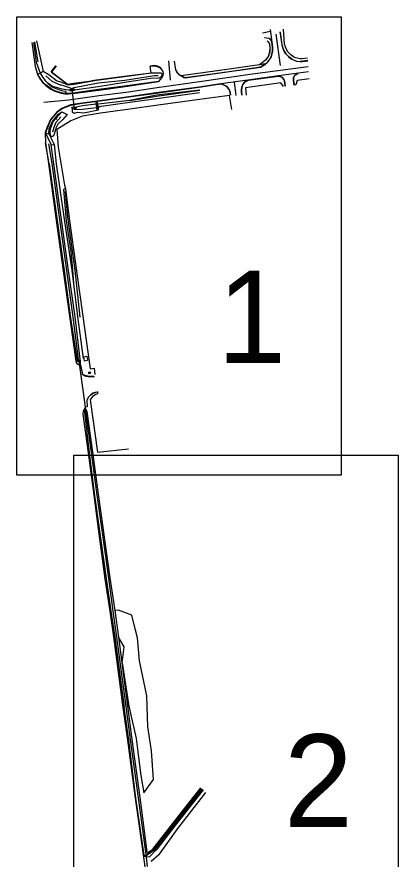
# Model space of a CAD drawing. Extents: x -866693 to -866303, y -1041966 to -1040244.
# Drawn here: x -866357.09 to -866344.74, y -1041790.49 to -1041763.2 of the extents above; entities that cross this region are included whole.
import ezdxf

# ---------------------------------------------------------------- set-up
doc = ezdxf.new("R2010")
doc.units = 0
doc.layers.add('Formát', color=7, linetype='Continuous')
doc.layers.add('Legenda', color=7, linetype='Continuous')

msp = doc.modelspace()

# ---------------------------------------------------------------- linework, layer by layer
at = {"layer": 'Legenda'}
for p, q in [((-866348.876, -1041763.675), (-866349.136, -1041763.734)), ((-866348.826, -1041764.023), (-866348.875, -1041763.608)), ((-866356.452, -1041763.975), (-866356.243, -1041764.972)), ((-866348.708, -1041763.762), (-866348.566, -1041764.773)), ((-866356.609, -1041764.036), (-866356.499, -1041764.813)), ((-866356.555, -1041764.03), (-866356.468, -1041764.665)), ((-866356.406, -1041764.659), (-866356.509, -1041764.007)), ((-866356.468, -1041764.665), (-866356.333, -1041765.029)), ((-866352.746, -1041765.022), (-866352.779, -1041764.799)), ((-866352.739, -1041765.027), (-866352.771, -1041764.804)), ((-866352.184, -1041764.624), (-866352.13, -1041765.247)), ((-866349.046, -1041764.728), (-866349.228, -1041764.754)), ((-866352.417, -1041765.021), (-866352.739, -1041765.027)), ((-866349.985, -1041765.749), (-866350.047, -1041765.314)), ((-866349.517, -1041765.253), (-866349.518, -1041765.249)), ((-866348.617, -1041765.135), (-866349.517, -1041765.253)), ((-866355.511, -1041765.61), (-866355.523, -1041765.68)), ((-866355.305, -1041765.551), (-866355.308, -1041765.527)), ((-866355.229, -1041766.165), (-866355.305, -1041765.55)), ((-866352.57, -1041765.771), (-866351.171, -1041765.58)), ((-866353.434, -1041765.908), (-866352.57, -1041765.771)), ((-866355.306, -1041766.168), (-866355.246, -1041766.167)), ((-866355.227, -1041766.199), (-866355.225, -1041766.165)), ((-866354.97, -1041766.083), (-866355.159, -1041766.122)), ((-866355.797, -1041766.529), (-866355.822, -1041766.493)), ((-866356.159, -1041766.964), (-866355.98, -1041767.349)), ((-866356.061, -1041766.989), (-866355.888, -1041767.34)), ((-866356.041, -1041767.959), (-866356.162, -1041767.281)), ((-866355.29, -1041771.401), (-866355.262, -1041771.827)), ((-866355.088, -1041774.36), (-866354.872, -1041775.924)), ((-866354.932, -1041774.212), (-866354.821, -1041774.197)), ((-866354.932, -1041774.212), (-866354.914, -1041774.341)), ((-866354.931, -1041774.213), (-866354.823, -1041774.198)), ((-866354.931, -1041774.213), (-866354.913, -1041774.34)), ((-866354.914, -1041774.341), (-866354.803, -1041774.326)), ((-866354.913, -1041774.34), (-866354.805, -1041774.325)), ((-866354.823, -1041774.198), (-866354.805, -1041774.325)), ((-866354.821, -1041774.197), (-866354.803, -1041774.326)), ((-866354.776, -1041774.71), (-866354.716, -1041774.703)), ((-866354.776, -1041774.71), (-866354.772, -1041774.754)), ((-866354.774, -1041774.712), (-866354.717, -1041774.705)), ((-866354.774, -1041774.712), (-866354.771, -1041774.752)), ((-866354.772, -1041774.754), (-866354.712, -1041774.747)), ((-866354.771, -1041774.752), (-866354.714, -1041774.745)), ((-866354.717, -1041774.705), (-866354.714, -1041774.745)), ((-866354.716, -1041774.703), (-866354.712, -1041774.747)), ((-866354.708, -1041775.46), (-866354.768, -1041775.526)), ((-866354.624, -1041775.399), (-866354.708, -1041775.46)), ((-866354.509, -1041775.357), (-866354.624, -1041775.399)), ((-866354.509, -1041775.357), (-866354.512, -1041775.354)), ((-866354.824, -1041775.621), (-866354.829, -1041775.618)), ((-866354.768, -1041775.526), (-866354.824, -1041775.621)), ((-866354.898, -1041775.902), (-866354.904, -1041776.005)), ((-866354.904, -1041776.005), (-866354.746, -1041777.325)), ((-866354.872, -1041775.924), (-866354.866, -1041775.986)), ((-866354.866, -1041775.986), (-866354.688, -1041777.315)), ((-866354.823, -1041775.985), (-866354.643, -1041777.308)), ((-866354.746, -1041777.325), (-866354.572, -1041778.706)), ((-866354.688, -1041777.315), (-866354.502, -1041778.697)), ((-866354.643, -1041777.308), (-866354.46, -1041778.663)), ((-866354.572, -1041778.706), (-866354.425, -1041779.772)), ((-866354.502, -1041778.697), (-866354.354, -1041779.755)), ((-866354.46, -1041778.663), (-866354.308, -1041779.74)), ((-866354.425, -1041779.772), (-866354.196, -1041781.395)), ((-866354.354, -1041779.755), (-866354.129, -1041781.381)), ((-866354.308, -1041779.74), (-866354.077, -1041781.37)), ((-866354.196, -1041781.395), (-866354.045, -1041782.456)), ((-866354.129, -1041781.381), (-866353.984, -1041782.449)), ((-866354.077, -1041781.37), (-866353.924, -1041782.429)), ((-866354.045, -1041782.456), (-866353.924, -1041783.291)), ((-866353.984, -1041782.449), (-866353.866, -1041783.294)), ((-866353.8, -1041782.422), (-866353.924, -1041782.429)), ((-866353.924, -1041782.429), (-866353.796, -1041783.301)), ((-866353.373, -1041782.588), (-866353.8, -1041782.422)), ((-866353.255, -1041783.029), (-866353.373, -1041782.588)), ((-866353.19, -1041783.317), (-866353.255, -1041783.029)), ((-866353.924, -1041783.291), (-866353.617, -1041785.568)), ((-866353.866, -1041783.294), (-866353.558, -1041785.547)), ((-866353.796, -1041783.301), (-866353.51, -1041785.536)), ((-866353.621, -1041783.609), (-866353.796, -1041783.301)), ((-866353.121, -1041784.06), (-866353.19, -1041783.317)), ((-866353.681, -1041784.123), (-866353.621, -1041783.609)), ((-866353.681, -1041784.123), (-866353.47, -1041785.529)), ((-866352.877, -1041785.197), (-866353.121, -1041784.06)), ((-866352.853, -1041786.204), (-866352.877, -1041785.197)), ((-866353.558, -1041785.547), (-866353.417, -1041786.616)), ((-866353.51, -1041785.536), (-866353.363, -1041786.612)), ((-866353.47, -1041785.529), (-866353.232, -1041786.582)), ((-866353.465, -1041786.632), (-866353.617, -1041785.568)), ((-866352.731, -1041786.979), (-866352.853, -1041786.204)), ((-866353.238, -1041788.51), (-866353.465, -1041786.632)), ((-866353.417, -1041786.616), (-866353.163, -1041788.5)), ((-866353.363, -1041786.612), (-866353.108, -1041788.493)), ((-866353.232, -1041786.582), (-866353.147, -1041787.179)), ((-866353.147, -1041787.179), (-866353.077, -1041787.777)), ((-866352.667, -1041787.909), (-866352.731, -1041786.979)), ((-866353.077, -1041787.777), (-866352.983, -1041788.336)), ((-866352.983, -1041788.336), (-866352.667, -1041787.909)), ((-866352.044, -1041789.33), (-866351.131, -1041788.18)), ((-866352.035, -1041789.354), (-866351.113, -1041788.193)), ((-866351.078, -1041788.218), (-866352.01, -1041789.373)), ((-866351.062, -1041788.236), (-866351.973, -1041789.406)), ((-866352.973, -1041790.356), (-866353.238, -1041788.51)), ((-866353.163, -1041788.5), (-866352.91, -1041790.339)), ((-866353.108, -1041788.493), (-866352.883, -1041790.247)), ((-866351.879, -1041789.489), (-866350.973, -1041788.332)), ((-866352.684, -1041790.168), (-866352.044, -1041789.33)), ((-866352.666, -1041790.181), (-866352.035, -1041789.354)), ((-866352.01, -1041789.373), (-866352.641, -1041790.199)), ((-866351.973, -1041789.406), (-866352.546, -1041790.157)), ((-866352.468, -1041790.32), (-866351.879, -1041789.489)), ((-866352.848, -1041790.275), (-866352.684, -1041790.168)), ((-866352.848, -1041790.316), (-866352.666, -1041790.181)), ((-866352.579, -1041790.197), (-866352.612, -1041790.22)), ((-866352.546, -1041790.157), (-866352.579, -1041790.197)), ((-866352.962, -1041790.403), (-866353.006, -1041790.332)), ((-866352.961, -1041790.371), (-866352.973, -1041790.356)), ((-866352.869, -1041790.421), (-866352.962, -1041790.403)), ((-866352.93, -1041790.383), (-866352.961, -1041790.371)), ((-866352.891, -1041790.377), (-866352.93, -1041790.383)), ((-866352.91, -1041790.339), (-866352.848, -1041790.316)), ((-866352.91, -1041790.339), (-866352.867, -1041790.725)), ((-866352.857, -1041790.348), (-866352.891, -1041790.377)), ((-866352.883, -1041790.247), (-866352.866, -1041790.271)), ((-866352.795, -1041790.415), (-866352.869, -1041790.421)), ((-866352.866, -1041790.271), (-866352.848, -1041790.275)), ((-866352.834, -1041790.341), (-866352.857, -1041790.348)), ((-866352.641, -1041790.199), (-866352.834, -1041790.341)), ((-866352.612, -1041790.22), (-866352.795, -1041790.415)), ((-866352.744, -1041790.553), (-866352.491, -1041790.333)), ((-866352.491, -1041790.333), (-866352.468, -1041790.32))]:
    msp.add_line(p, q, dxfattribs=at)
for points in [[(-866357.092, -1041763.201), (-866346.592, -1041763.201), (-866346.592, -1041778.051), (-866357.092, -1041778.051)], [(-866355.228, -1041765.578), (-866355.23, -1041765.577), (-866355.233, -1041765.548), (-866355.23, -1041765.547)], [(-866355.307, -1041766.14), (-866355.303, -1041766.166), (-866355.306, -1041766.168)], [(-866354.533, -1041765.992), (-866354.497, -1041766.228), (-866354.447, -1041766.217), (-866354.476, -1041765.98)], [(-866355.63, -1041766.278), (-866355.467, -1041766.363), (-866355.618, -1041766.533), (-866355.77, -1041766.675), (-866355.831, -1041766.804), (-866355.841, -1041766.847), (-866355.895, -1041767.042), (-866355.951, -1041767.084), (-866355.994, -1041767.07), (-866356.015, -1041766.962), (-866355.998, -1041766.824), (-866355.918, -1041766.595)], [(-866355.243, -1041777.397), (-866344.743, -1041777.397), (-866344.743, -1041792.247), (-866355.243, -1041792.247)]]:
    msp.add_lwpolyline(points, close=True, dxfattribs=at)
for points in [[(-866348.563, -1041763.697), (-866348.507, -1041764.108), (-866348.482, -1041764.21), (-866348.449, -1041764.296), (-866348.383, -1041764.4), (-866348.31, -1041764.48), (-866348.285, -1041764.502), (-866348.184, -1041764.57), (-866348.109, -1041764.603), (-866348.031, -1041764.634), (-866347.918, -1041764.652), (-866347.842, -1041764.648), (-866347.668, -1041764.626)], [(-866348.184, -1041764.57), (-866348.182, -1041764.565), (-866348.28, -1041764.497), (-866348.305, -1041764.476), (-866348.377, -1041764.395), (-866348.442, -1041764.294), (-866348.474, -1041764.206), (-866348.501, -1041764.105), (-866348.559, -1041763.688)], [(-866347.679, -1041764.536), (-866347.861, -1041764.557), (-866347.914, -1041764.559), (-866348.012, -1041764.542), (-866348.07, -1041764.526), (-866348.128, -1041764.497), (-866348.219, -1041764.433), (-866348.245, -1041764.414), (-866348.315, -1041764.335), (-866348.359, -1041764.26), (-866348.396, -1041764.174), (-866348.419, -1041764.082), (-866348.461, -1041763.597)], [(-866352, -1041764.633), (-866351.957, -1041764.919), (-866351.908, -1041765.007), (-866351.853, -1041765.06), (-866351.747, -1041765.128), (-866351.679, -1041765.166), (-866351.643, -1041765.178), (-866350.21, -1041764.977), (-866349.204, -1041764.834), (-866349.036, -1041764.73), (-866348.959, -1041764.662), (-866348.883, -1041764.562), (-866348.849, -1041764.498), (-866348.82, -1041764.391), (-866348.803, -1041764.311), (-866348.802, -1041764.188), (-866348.826, -1041764.023), (-866348.857, -1041763.96), (-866348.892, -1041763.919), (-866348.917, -1041763.901), (-866349.067, -1041763.877)], [(-866348.986, -1041763.978), (-866348.939, -1041764.008), (-866348.914, -1041764.087), (-866348.9, -1041764.209), (-866348.904, -1041764.319), (-866348.915, -1041764.379), (-866348.94, -1041764.457), (-866348.976, -1041764.518), (-866349.041, -1041764.599), (-866349.092, -1041764.65), (-866349.23, -1041764.751), (-866350.221, -1041764.892), (-866351.767, -1041765.109)], [(-866348.81, -1041764.312), (-866348.807, -1041764.189), (-866348.83, -1041764.024), (-866348.856, -1041763.966), (-866348.895, -1041763.922), (-866348.917, -1041763.903), (-866349.06, -1041763.881)], [(-866348.986, -1041763.976), (-866348.938, -1041764.006), (-866348.912, -1041764.085), (-866348.896, -1041764.208)], [(-866348.896, -1041764.208), (-866348.899, -1041764.319), (-866348.913, -1041764.379), (-866348.938, -1041764.459), (-866348.972, -1041764.52), (-866349.034, -1041764.601), (-866349.092, -1041764.653), (-866349.228, -1041764.754), (-866350.219, -1041764.895), (-866351.765, -1041765.11)], [(-866349.046, -1041764.728), (-866349.04, -1041764.724), (-866348.964, -1041764.656), (-866348.891, -1041764.558), (-866348.856, -1041764.496), (-866348.81, -1041764.312)], [(-866356.499, -1041764.813), (-866356.419, -1041765.059), (-866356.354, -1041765.192), (-866356.247, -1041765.336), (-866356.15, -1041765.43), (-866355.991, -1041765.545), (-866355.865, -1041765.606), (-866355.66, -1041765.675), (-866355.535, -1041765.694), (-866355.425, -1041765.695), (-866355.199, -1041765.675), (-866354.441, -1041765.572), (-866353.588, -1041765.453), (-866352.501, -1041765.294), (-866352.386, -1041765.167), (-866352.351, -1041765.1), (-866352.343, -1041765.024), (-866352.355, -1041764.972), (-866352.384, -1041764.924), (-866352.433, -1041764.867), (-866352.474, -1041764.835), (-866352.542, -1041764.801), (-866352.619, -1041764.778), (-866352.779, -1041764.799)], [(-866356.217, -1041765.966), (-866355.413, -1041765.887), (-866354.429, -1041765.75), (-866353.475, -1041765.633), (-866352.625, -1041765.506), (-866351.179, -1041765.296), (-866349.461, -1041765.052), (-866347.652, -1041764.805)], [(-866352.739, -1041765.027), (-866353.611, -1041765.143), (-866354.513, -1041765.258), (-866355.236, -1041765.36), (-866355.455, -1041765.391), (-866355.981, -1041764.987), (-866355.827, -1041764.792)], [(-866355.816, -1041764.79), (-866355.97, -1041764.989), (-866355.453, -1041765.382), (-866355.256, -1041765.354), (-866354.665, -1041765.273)], [(-866352.771, -1041764.804), (-866352.614, -1041764.787), (-866352.545, -1041764.809), (-866352.477, -1041764.842), (-866352.438, -1041764.873), (-866352.39, -1041764.928), (-866352.362, -1041764.973), (-866352.35, -1041765.023), (-866352.359, -1041765.099), (-866352.394, -1041765.166), (-866352.505, -1041765.291), (-866353.601, -1041765.447)], [(-866351.993, -1041764.632), (-866351.953, -1041764.918), (-866351.902, -1041765.004), (-866351.849, -1041765.056), (-866351.767, -1041765.109), (-866351.765, -1041765.11), (-866351.741, -1041765.123), (-866351.739, -1041765.12), (-866351.697, -1041765.142), (-866351.641, -1041765.165), (-866351.643, -1041765.17), (-866350.212, -1041764.971), (-866349.204, -1041764.825), (-866349.046, -1041764.728)], [(-866347.669, -1041764.619), (-866347.844, -1041764.642), (-866347.919, -1041764.646), (-866347.918, -1041764.652)], [(-866356.419, -1041765.059), (-866356.333, -1041765.029), (-866356.248, -1041765.163), (-866356.175, -1041765.261), (-866356.085, -1041765.35), (-866355.953, -1041765.473), (-866355.829, -1041765.524), (-866355.642, -1041765.582), (-866355.511, -1041765.61)], [(-866353.601, -1041765.447), (-866354.445, -1041765.557), (-866355.2, -1041765.664), (-866355.424, -1041765.681), (-866355.532, -1041765.68), (-866355.655, -1041765.659), (-866355.859, -1041765.593), (-866355.982, -1041765.532), (-866356.142, -1041765.416), (-866356.237, -1041765.326), (-866356.342, -1041765.183), (-866356.419, -1041765.059)], [(-866354.517, -1041765.263), (-866355.234, -1041765.389), (-866355.433, -1041765.416), (-866355.632, -1041765.323), (-866355.812, -1041765.269), (-866356.053, -1041765.078), (-866356.243, -1041764.972), (-866356.333, -1041765.029)], [(-866347.644, -1041764.982), (-866348.618, -1041765.116), (-866349.535, -1041765.243), (-866350.557, -1041765.385), (-866351.186, -1041765.474), (-866352.586, -1041765.668), (-866353.465, -1041765.789), (-866354.405, -1041765.92), (-866354.976, -1041765.996), (-866355.354, -1041766.055), (-866355.636, -1041766.171), (-866355.801, -1041766.29), (-866356.002, -1041766.524), (-866356.124, -1041766.792), (-866356.17, -1041766.959), (-866356.162, -1041767.281), (-866356.072, -1041767.954), (-866355.805, -1041769.87), (-866355.596, -1041771.425), (-866355.38, -1041772.972), (-866355.185, -1041774.356), (-866355.149, -1041774.434), (-866355.1, -1041774.461), (-866355.036, -1041774.476), (-866354.968, -1041774.783), (-866354.888, -1041774.825), (-866354.843, -1041774.84), (-866354.728, -1041774.861), (-866354.58, -1041774.851)], [(-866352.417, -1041765.021), (-866352.39, -1041765.07), (-866352.426, -1041765.152), (-866352.486, -1041765.184), (-866352.754, -1041765.201), (-866353.593, -1041765.328), (-866354.458, -1041765.463), (-866355.228, -1041765.578)], [(-866352.746, -1041765.022), (-866353.618, -1041765.138), (-866354.52, -1041765.253), (-866354.665, -1041765.273)], [(-866347.992, -1041765.045), (-866348.011, -1041765.048), (-866348.036, -1041765.057), (-866348.056, -1041765.068), (-866348.077, -1041765.084), (-866348.095, -1041765.101), (-866348.115, -1041765.121), (-866348.125, -1041765.141), (-866348.141, -1041765.18), (-866348.144, -1041765.204), (-866348.143, -1041765.262), (-866348.122, -1041765.41)], [(-866347.992, -1041765.045), (-866347.991, -1041765.051), (-866348.032, -1041765.064), (-866348.051, -1041765.075), (-866348.074, -1041765.09), (-866348.108, -1041765.126), (-866348.134, -1041765.182), (-866348.137, -1041765.205), (-866348.136, -1041765.261), (-866348.114, -1041765.406)], [(-866356.149, -1041765.109), (-866355.964, -1041765.286), (-866355.689, -1041765.408), (-866355.662, -1041765.407), (-866355.402, -1041765.487), (-866355.308, -1041765.527), (-866355.233, -1041765.49), (-866354.463, -1041765.339), (-866353.6, -1041765.254), (-866352.636, -1041765.105), (-866352.515, -1041765.106)], [(-866355.381, -1041765.564), (-866355.433, -1041765.575), (-866355.629, -1041765.547), (-866355.813, -1041765.486), (-866355.943, -1041765.454), (-866356.085, -1041765.35)], [(-866349.535, -1041765.243), (-866349.608, -1041765.26), (-866349.672, -1041765.288), (-866349.736, -1041765.338), (-866349.784, -1041765.402), (-866349.82, -1041765.486), (-866349.832, -1041765.562), (-866349.829, -1041765.628), (-866349.816, -1041765.741)], [(-866349.518, -1041765.249), (-866349.536, -1041765.251), (-866349.605, -1041765.265), (-866349.67, -1041765.294), (-866349.73, -1041765.341), (-866349.78, -1041765.408), (-866349.81, -1041765.487), (-866349.821, -1041765.563), (-866349.817, -1041765.63), (-866349.808, -1041765.741)], [(-866348.461, -1041765.457), (-866348.547, -1041765.343), (-866349.692, -1041765.506), (-866349.666, -1041765.74)], [(-866348.395, -1041765.449), (-866348.418, -1041765.289), (-866348.42, -1041765.278), (-866348.43, -1041765.242), (-866348.437, -1041765.226), (-866348.449, -1041765.207), (-866348.475, -1041765.176), (-866348.504, -1041765.158), (-866348.529, -1041765.146), (-866348.564, -1041765.136), (-866348.618, -1041765.116)], [(-866348.617, -1041765.135), (-866348.617, -1041765.135), (-866348.617, -1041765.129), (-866348.618, -1041765.116)], [(-866348.399, -1041765.449), (-866348.427, -1041765.278), (-866348.443, -1041765.232), (-866348.482, -1041765.182), (-866348.53, -1041765.154), (-866348.568, -1041765.142), (-866348.617, -1041765.129)], [(-866347.622, -1041765.207), (-866348.008, -1041765.264), (-866348.059, -1041765.403), (-866348.108, -1041765.41)], [(-866350.174, -1041765.736), (-866350.185, -1041765.661), (-866350.199, -1041765.605), (-866350.224, -1041765.549), (-866350.269, -1041765.493), (-866350.319, -1041765.451), (-866350.365, -1041765.424), (-866350.406, -1041765.406), (-866350.45, -1041765.393), (-866350.492, -1041765.386), (-866350.536, -1041765.39), (-866350.555, -1041765.392), (-866350.557, -1041765.397), (-866351.198, -1041765.487), (-866352.584, -1041765.68), (-866353.463, -1041765.804), (-866354.398, -1041765.933), (-866354.972, -1041766.011), (-866355.35, -1041766.069), (-866355.63, -1041766.185), (-866355.671, -1041766.209), (-866355.792, -1041766.302), (-866355.99, -1041766.531), (-866356.106, -1041766.802), (-866356.159, -1041766.964), (-866356.17, -1041766.959)], [(-866355.381, -1041765.564), (-866355.323, -1041765.553), (-866355.305, -1041765.551), (-866355.292, -1041765.55), (-866355.23, -1041765.547)], [(-866355.233, -1041765.548), (-866355.381, -1041765.564), (-866355.377, -1041765.593), (-866355.23, -1041765.577)], [(-866351.171, -1041765.58), (-866352.573, -1041765.739), (-866353.434, -1041765.908), (-866354.365, -1041766.017), (-866354.471, -1041766.026)], [(-866350.167, -1041765.736), (-866350.176, -1041765.659), (-866350.19, -1041765.602), (-866350.221, -1041765.546), (-866350.264, -1041765.489), (-866350.315, -1041765.446), (-866350.36, -1041765.42), (-866350.402, -1041765.401), (-866350.449, -1041765.387), (-866350.491, -1041765.38), (-866350.557, -1041765.385)], [(-866350.128, -1041766.199), (-866350.207, -1041765.746), (-866351.173, -1041765.875), (-866352.516, -1041766.064), (-866353.431, -1041766.19), (-866354.383, -1041766.318), (-866354.966, -1041766.414), (-866355.339, -1041766.567), (-866355.792, -1041766.853), (-866355.751, -1041767.427), (-866355.551, -1041768.65), (-866355.521, -1041768.774), (-866355.483, -1041769.042), (-866355.386, -1041769.8), (-866355.162, -1041771.439), (-866354.966, -1041772.827), (-866354.719, -1041774.598), (-866354.592, -1041774.582), (-866354.569, -1041774.785)], [(-866354.358, -1041766.09), (-866353.436, -1041765.961), (-866352.555, -1041765.846), (-866351.177, -1041765.647)], [(-866355.3, -1041766.166), (-866355.157, -1041766.15), (-866355.159, -1041766.122), (-866355.307, -1041766.14)], [(-866355.306, -1041766.168), (-866355.301, -1041766.279), (-866355.231, -1041766.322), (-866355.131, -1041766.291), (-866354.923, -1041766.311), (-866354.497, -1041766.228)], [(-866355.246, -1041766.167), (-866355.225, -1041766.165), (-866355.209, -1041766.161), (-866355.187, -1041766.161), (-866355.154, -1041766.148)], [(-866355.227, -1041766.199), (-866354.963, -1041766.193), (-866354.517, -1041766.14)], [(-866355.157, -1041766.15), (-866355.154, -1041766.148), (-866355.159, -1041766.122)], [(-866354.526, -1041766.035), (-866354.97, -1041766.083)], [(-866354.533, -1041765.992), (-866354.517, -1041766.14), (-866354.497, -1041766.228)], [(-866354.447, -1041766.217), (-866354.453, -1041766.132), (-866354.476, -1041765.98)], [(-866354.453, -1041766.132), (-866354.358, -1041766.09)], [(-866356.159, -1041766.964), (-866356.061, -1041766.989), (-866356.046, -1041766.816), (-866355.937, -1041766.586), (-866355.746, -1041766.355), (-866355.63, -1041766.278)], [(-866355.669, -1041766.441), (-866355.834, -1041766.627), (-866355.899, -1041766.787), (-866355.935, -1041766.939)], [(-866356.071, -1041767.317), (-866355.958, -1041767.957), (-866355.695, -1041769.855), (-866355.483, -1041771.421), (-866355.279, -1041772.935), (-866355.102, -1041774.289), (-866355.088, -1041774.36)], [(-866355.036, -1041774.476), (-866355.036, -1041774.344), (-866355.046, -1041774.292), (-866355.206, -1041772.923), (-866355.421, -1041771.416), (-866355.64, -1041769.848), (-866355.899, -1041767.963), (-866355.98, -1041767.349), (-866355.888, -1041767.34), (-866355.82, -1041767.961), (-866355.546, -1041769.832), (-866355.316, -1041771.406), (-866355.123, -1041772.913), (-866354.946, -1041774.274)], [(-866356.041, -1041767.959), (-866355.775, -1041769.871), (-866355.555, -1041771.422), (-866355.356, -1041772.966), (-866355.144, -1041774.345), (-866355.107, -1041774.369), (-866355.081, -1041774.364), (-866355.07, -1041774.351), (-866355.046, -1041774.292)], [(-866355.521, -1041768.774), (-866355.581, -1041768.793), (-866355.499, -1041769.81), (-866355.449, -1041770.09), (-866355.341, -1041770.816), (-866355.29, -1041771.401)], [(-866355.522, -1041768.856), (-866355.448, -1041769.687), (-866355.209, -1041771.405), (-866355.054, -1041772.928)], [(-866354.968, -1041774.783), (-866354.964, -1041774.779), (-866354.885, -1041774.817)], [(-866354.598, -1041774.847), (-866354.726, -1041774.855), (-866354.843, -1041774.832), (-866354.885, -1041774.817)], [(-866354.512, -1041775.354), (-866354.628, -1041775.396), (-866354.711, -1041775.454), (-866354.77, -1041775.522), (-866354.829, -1041775.618), (-866354.813, -1041775.831), (-866354.88, -1041775.843), (-866354.949, -1041775.982), (-866354.95, -1041776.076), (-866354.784, -1041777.328), (-866354.6, -1041778.694), (-866354.456, -1041779.783), (-866354.241, -1041781.404), (-866354.077, -1041782.458), (-866353.961, -1041783.283), (-866353.658, -1041785.579), (-866353.508, -1041786.636), (-866353.262, -1041788.508), (-866353.006, -1041790.332), (-866352.946, -1041790.738)], [(-866354.484, -1041775.34), (-866354.475, -1041775.416), (-866354.53, -1041775.433), (-866354.638, -1041775.5), (-866354.714, -1041775.603), (-866354.485, -1041777.307), (-866353.481, -1041777.196)], [(-866354.898, -1041775.902), (-866354.855, -1041775.908), (-866354.823, -1041775.985)]]:
    msp.add_lwpolyline(points, dxfattribs=at)

# ---------------------------------------------------------------- texts
at = {"layer": 'Formát'}
for s, p in [('1', (-866350.6, -1041774.419)), ('2', (-866348.441, -1041789.443))]:
    msp.add_text(s, height=3, dxfattribs=at).set_placement(p)

doc.saveas('drawing.dxf')
